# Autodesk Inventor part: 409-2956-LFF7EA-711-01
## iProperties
Created: 2010-06
Part Number: 409-2956-LFF7EA-711-01
Material: Sch40 CS PIPE SEAMLESS
Description: PIPE
Document SubType Name: Modeling
Designer: S. Boerckel
Engineer: Steve Boerckel
Mass: 4223.4 g
Surface Area: 1828.43 cm^2
Volume: 538.013 cm^3
Density: 7.85 g/cm^3
Cost Center: 4"
SMR: =<COST CENTER> - <Material>
Length: 10.344 in
Title: 3"
Author: S. Boerckel
Revision Number: A
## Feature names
1. Extrusion1
